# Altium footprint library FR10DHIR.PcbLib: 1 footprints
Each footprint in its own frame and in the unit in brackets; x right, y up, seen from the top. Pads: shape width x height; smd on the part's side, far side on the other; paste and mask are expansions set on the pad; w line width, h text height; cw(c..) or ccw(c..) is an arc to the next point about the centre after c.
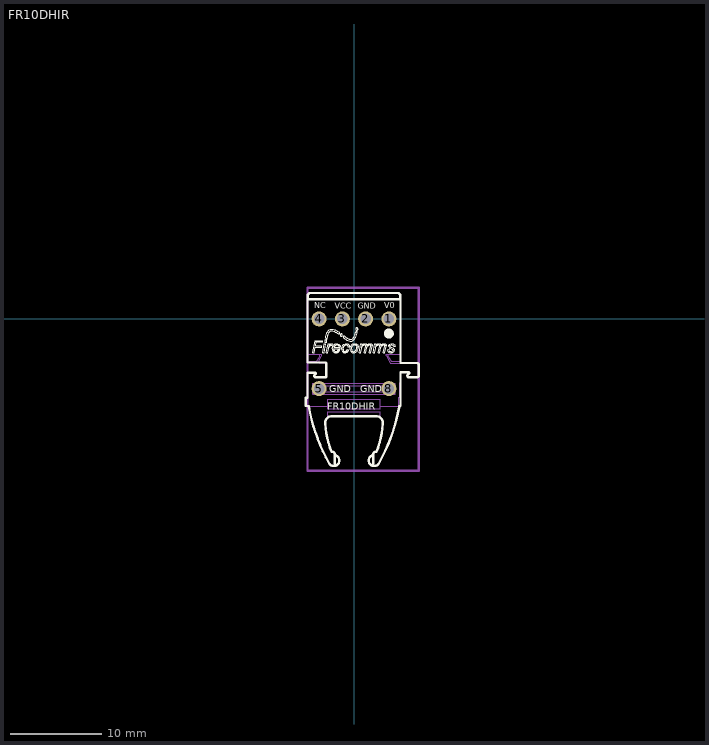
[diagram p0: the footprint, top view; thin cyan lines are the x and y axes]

## FR10DHIR [mil] "Inverting RedLink® 10 MBd Receiver Horizontal"
height 300
pads (6):
  round 65 hole 45: 1(150,0) 2(50,0) 3(-50,0) 4(-150,0) 5(-150,-300) 8(150,-300)
Top Overlay:
  drawing of 1776 lines, arcs and shapes, not listed
  text "GND" at -106.3,-314.96 h30
  text "GND" at 27.56,-314.96 h30
  text "NC" at -170,45 h25
  text "VCC" at -82.68,43.31 h25
  text "GND" at 15.75,43.31 h25
  text "V0" at 130,45 h25
  text "FR10DHIR" at -115,-390 h30
Mechanical 2:
  lines w10: 278.74,-653.54 278.74,133.26 278.14,133.86 -200,133.86 -200,-653.54 279,-653.54
Mechanical 19:
  drawing of 1055 lines, arcs and shapes, not listed
3D body "Horizontal RedLink Connector.stp": height 301.22, standoff -144.78, extent -207.87,-627.68 278.75,116.41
